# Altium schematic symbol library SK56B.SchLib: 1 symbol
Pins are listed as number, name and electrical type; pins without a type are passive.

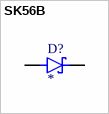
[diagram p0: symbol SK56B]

## SK56B
designator D?
5A, 60V, Schottky Rectifier; MF: Taiwan Semiconductor; MP: SK56B
footprint DIO_SK56B
pins: A, C K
